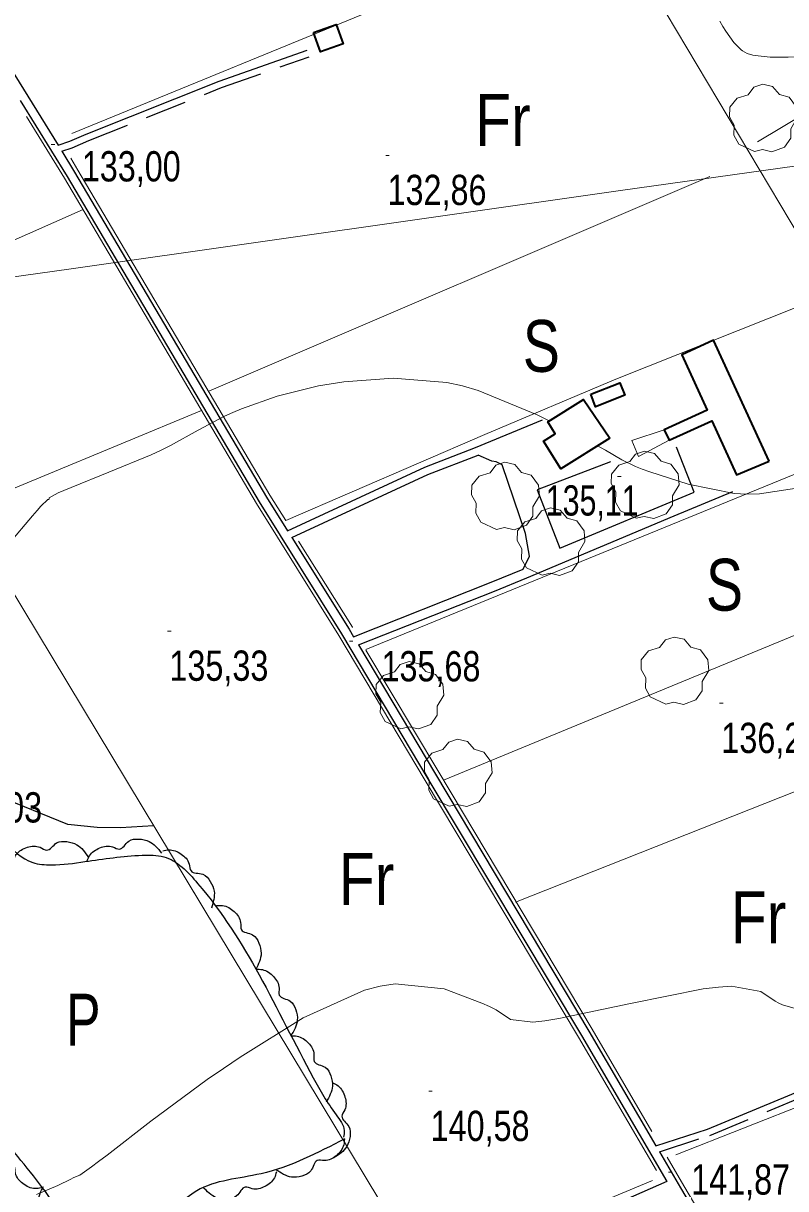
# Model space of a CAD drawing. Extents: x 487425 to 492029, y 4383576 to 4386788.
# Drawn here: x 489184.7 to 489405.2, y 4384585.2 to 4384922.2 of the extents above; entities that cross this region are included whole.
import ezdxf
from ezdxf.enums import TextEntityAlignment as Align

# ---------------------------------------------------------------- set-up
doc = ezdxf.new("R2010")
doc.units = 0
doc.header["$LTSCALE"] = 4
doc.linetypes.add('LONG_DASHED', pattern=[7.5, 6, -1.5])
doc.linetypes.add('MEDIUM_DASHED', pattern=[4.5, 3, -1.5])
for name, color, linetype, lineweight in [('24', 7, 'Continuous', 13), ('25', 7, 'LONG_DASHED', 25), ('27', 7, 'Continuous', 25), ('29', 7, 'Continuous', 13), ('38', 7, 'Continuous', 25), ('47', 7, 'Continuous', 35), ('51', 7, 'Continuous', 13), ('7', 7, 'Continuous', 13), ('9', 7, 'Continuous', 13)]:
    doc.layers.add(name, color=color, linetype=linetype, lineweight=lineweight)
doc.layers.add('31', color=7, linetype='Continuous')

msp = doc.modelspace()

# ---------------------------------------------------------------- linework, layer by layer
at = {"layer": '24'}
msp.add_lwpolyline([(488954.49, 4384817.11), (489198.5, 4384851.16), (489357.39, 4384873.86), (489601.4, 4384907.91), (489794.34, 4384879.53), (490083.75, 4384822.79), (490248.31, 4384800.09), (490395.85, 4384817.11), (490526.37, 4384822.79), (490764.71, 4384947.63), (491088.16, 4385117.87), (491252.72, 4385202.99), (491256.7, 4385199.2)], dxfattribs=at)
at = {"layer": '25'}
msp.add_lwpolyline([(489222.36, 4384690.19), (489212.78, 4384689.59), (489206.03, 4384689.67), (489197.56, 4384690.51), (489164.93, 4384703.86), (489153.06, 4384702.65), (489149.95, 4384699.31), (489143.37, 4384687.6), (489140.48, 4384684.41)], dxfattribs=at)
at = {"layer": '27'}
for points in [[(489277.55, 4384599.65), (489253.43, 4384589.57), (489234.85, 4384584.61), (489229.17, 4384580.47), (489221.96, 4384572.75), (489221.7, 4384569.75), (489218.14, 4384566.64), (489212.8, 4384565.88), (489207.48, 4384566.39), (489199.58, 4384570.83), (489195.68, 4384577.18), (489182.16, 4384595.71), (489170.8, 4384606.34), (489161.36, 4384607.13), (489156.68, 4384605.3), (489150.43, 4384602.52), (489140.52, 4384602.56), (489136.88, 4384605.9), (489134.6, 4384609.23), (489133.91, 4384614.79), (489136.48, 4384623.16), (489142.17, 4384628.65), (489151.82, 4384632.89), (489159.74, 4384636.18), (489165.7, 4384639.11), (489160.81, 4384651.84), (489154, 4384659.2), (489144.07, 4384670.19), (489139.87, 4384677.29), (489142.09, 4384681.32), (489153.12, 4384687.94), (489165.33, 4384692.98), (489178.98, 4384685.7), (489187.39, 4384679.53), (489192.78, 4384678.86), (489202.47, 4384679.8), (489219.07, 4384681.64), (489225.29, 4384681.2), (489235.11, 4384673.51), (489252.89, 4384647.05), (489268.53, 4384617.31), (489275.16, 4384606.58), (489277.51, 4384602.05), (489277.33, 4384600.1)], [(489181.81, 4384680.34), (489182.66, 4384681.89), (489185.86, 4384683.94), (489189.55, 4384683.94), (489191.43, 4384683.13), (489194.33, 4384685.19), (489197.29, 4384685.58), (489200.18, 4384684.69), (489203.5, 4384681)], [(489203.08, 4384679.86), (489203.81, 4384681.48), (489206.83, 4384683.77), (489210.51, 4384684.07), (489212.46, 4384683.41), (489215.18, 4384685.69), (489218.1, 4384686.32), (489221.05, 4384685.66), (489224.65, 4384682.25)], [(489224.99, 4384682.9), (489226.74, 4384683.21), (489230.33, 4384681.99), (489232.64, 4384679.11), (489233.19, 4384677.13), (489236.61, 4384676.16), (489238.77, 4384674.1), (489239.88, 4384671.29), (489239.07, 4384666.39)], [(489240.55, 4384667.08), (489242.32, 4384667.11), (489245.68, 4384665.35), (489247.53, 4384662.16), (489247.76, 4384660.12), (489250.99, 4384658.63), (489252.81, 4384656.26), (489253.47, 4384653.31), (489251.92, 4384648.6)], [(489252.05, 4384648.67), (489253.82, 4384648.58), (489257.05, 4384646.58), (489258.65, 4384643.25), (489258.73, 4384641.2), (489261.85, 4384639.48), (489263.48, 4384636.98), (489263.93, 4384633.99), (489262.04, 4384629.41)], [(489262.08, 4384629.43), (489263.85, 4384629.35), (489267.1, 4384627.38), (489268.73, 4384624.08), (489268.84, 4384622.03), (489271.97, 4384620.34), (489273.63, 4384617.86), (489274.11, 4384614.87), (489272.27, 4384610.27)], [(489274.17, 4384615.85), (489275.72, 4384614.97), (489277.71, 4384611.74), (489277.65, 4384608.05), (489276.81, 4384606.18), (489278.83, 4384603.25), (489279.18, 4384600.29), (489278.24, 4384597.41), (489274.5, 4384594.15)], [(489189.84, 4384585.45), (489188.08, 4384585.26), (489184.57, 4384586.7), (489182.44, 4384589.72), (489182.03, 4384591.73), (489178.68, 4384592.92), (489176.66, 4384595.12), (489175.73, 4384598), (489176.84, 4384602.83)], [(489277.55, 4384599.65), (489277.36, 4384597.89), (489275.18, 4384594.78), (489271.77, 4384593.36), (489269.72, 4384593.39), (489267.83, 4384590.38), (489265.25, 4384588.89), (489262.24, 4384588.6), (489257.76, 4384590.74)], [(489257.88, 4384590.09), (489257.31, 4384588.41), (489254.51, 4384585.85), (489250.88, 4384585.21), (489248.88, 4384585.69), (489246.38, 4384583.16), (489243.53, 4384582.26), (489240.53, 4384582.64), (489236.63, 4384585.7)], [(489201.54, 4384567.2), (489199.77, 4384567.2), (489196.44, 4384569.03), (489194.67, 4384572.27), (489194.48, 4384574.31), (489191.28, 4384575.87), (489189.52, 4384578.27), (489188.91, 4384581.24), (489190.56, 4384585.92)]]:
    msp.add_spline(points, degree=3, dxfattribs=at)
at = {"layer": '29'}
for points in [[(489396.16, 4384885.12), (489391.62, 4384887.24), (489390.21, 4384889.78), (489390.31, 4384892.76), (489388.94, 4384895.17), (489388.98, 4384897.92), (489391.14, 4384900.52), (489394.33, 4384901.52), (489395.98, 4384903.71), (489398.55, 4384904.54), (489401.41, 4384903.89), (489403.36, 4384901.62), (489406.17, 4384900.8), (489408.3, 4384897.95), (489408.54, 4384894.82), (489406.66, 4384891.67), (489406.66, 4384888.99), (489404.84, 4384886.38), (489401.22, 4384885.04), (489398.45, 4384885.67)], [(489361.95, 4384779.05), (489357.41, 4384781.17), (489356, 4384783.71), (489356.1, 4384786.69), (489354.73, 4384789.1), (489354.77, 4384791.85), (489356.93, 4384794.45), (489360.12, 4384795.45), (489361.77, 4384797.64), (489364.34, 4384798.47), (489367.2, 4384797.82), (489369.15, 4384795.55), (489371.96, 4384794.73), (489374.09, 4384791.88), (489374.33, 4384788.75), (489372.45, 4384785.6), (489372.45, 4384782.92), (489370.63, 4384780.31), (489367.01, 4384778.97), (489364.24, 4384779.6)], [(489321.55, 4384775.84), (489317.01, 4384777.96), (489315.6, 4384780.5), (489315.7, 4384783.48), (489314.33, 4384785.89), (489314.37, 4384788.64), (489316.53, 4384791.24), (489319.72, 4384792.24), (489321.37, 4384794.43), (489323.94, 4384795.26), (489326.8, 4384794.61), (489328.75, 4384792.34), (489331.56, 4384791.52), (489333.69, 4384788.67), (489333.93, 4384785.54), (489332.05, 4384782.39), (489332.05, 4384779.71), (489330.23, 4384777.1), (489326.61, 4384775.76), (489323.84, 4384776.39)], [(489334.75, 4384762.63), (489330.21, 4384764.75), (489328.8, 4384767.29), (489328.9, 4384770.27), (489327.53, 4384772.68), (489327.57, 4384775.43), (489329.73, 4384778.03), (489332.92, 4384779.03), (489334.57, 4384781.22), (489337.14, 4384782.05), (489340, 4384781.4), (489341.95, 4384779.13), (489344.76, 4384778.31), (489346.89, 4384775.46), (489347.13, 4384772.33), (489345.25, 4384769.18), (489345.25, 4384766.5), (489343.43, 4384763.89), (489339.81, 4384762.55), (489337.04, 4384763.18)], [(489370.56, 4384725.31), (489366.02, 4384727.43), (489364.61, 4384729.97), (489364.71, 4384732.95), (489363.34, 4384735.36), (489363.38, 4384738.11), (489365.54, 4384740.71), (489368.73, 4384741.71), (489370.38, 4384743.9), (489372.95, 4384744.73), (489375.81, 4384744.08), (489377.76, 4384741.81), (489380.57, 4384740.99), (489382.7, 4384738.14), (489382.94, 4384735.01), (489381.06, 4384731.86), (489381.06, 4384729.18), (489379.24, 4384726.57), (489375.62, 4384725.23), (489372.85, 4384725.86)], [(489293.89, 4384718.23), (489289.35, 4384720.35), (489287.94, 4384722.89), (489288.04, 4384725.87), (489286.67, 4384728.28), (489286.71, 4384731.03), (489288.87, 4384733.63), (489292.06, 4384734.63), (489293.71, 4384736.82), (489296.28, 4384737.65), (489299.14, 4384737), (489301.09, 4384734.73), (489303.9, 4384733.91), (489306.03, 4384731.06), (489306.27, 4384727.93), (489304.39, 4384724.78), (489304.39, 4384722.1), (489302.57, 4384719.49), (489298.95, 4384718.15), (489296.18, 4384718.78)], [(489307.89, 4384695.79), (489303.35, 4384697.91), (489301.94, 4384700.45), (489302.04, 4384703.43), (489300.67, 4384705.84), (489300.71, 4384708.59), (489302.87, 4384711.19), (489306.06, 4384712.19), (489307.71, 4384714.38), (489310.28, 4384715.21), (489313.14, 4384714.56), (489315.09, 4384712.29), (489317.9, 4384711.47), (489320.03, 4384708.62), (489320.27, 4384705.49), (489318.39, 4384702.34), (489318.39, 4384699.66), (489316.57, 4384697.05), (489312.95, 4384695.71), (489310.18, 4384696.34)]]:
    msp.add_lwpolyline(points, close=True, dxfattribs=at)
at = {"layer": '38'}
for p, q in [((489170.75, 4384925.69), (489194.73, 4384886.93)), ((489315.44, 4384799.49), (489334.84, 4384807.49))]:
    msp.add_line(p, q, dxfattribs=at)
for points in [[(489194.73, 4384886.93), (489198.15, 4384888.06), (489202.87, 4384890.1), (489241.34, 4384905.42), (489266.74, 4384914.37)], [(489183.8, 4384899.8), (489197.37, 4384877.86), (489252.87, 4384783.82), (489276.74, 4384745.66), (489301.69, 4384703.76), (489346.08, 4384629.51), (489370.77, 4384587.28)], [(489195.79, 4384885.19), (489199.53, 4384879.16), (489255.03, 4384785.13), (489261.07, 4384775.47)], [(489354.5, 4384795.41), (489333.33, 4384787.32), (489339.82, 4384770.44), (489378.71, 4384786.58), (489373.61, 4384799.62)], [(489261.07, 4384775.47), (489300.77, 4384793.86), (489315.44, 4384799.49)], [(489262.31, 4384773.5), (489301.67, 4384791.73), (489316.27, 4384797.33)], [(489329.3, 4384764.35), (489331.09, 4384768.14), (489329.96, 4384774.68), (489323.21, 4384794.49), (489321.42, 4384795.41), (489320.22, 4384795.57), (489316.27, 4384797.33)], [(489330.33, 4384761.82), (489372.93, 4384779.74), (489389.89, 4384786.83)], [(489262.31, 4384773.5), (489278.9, 4384746.97), (489280.17, 4384744.83)], [(489280.17, 4384744.83), (489319.96, 4384760.55), (489329.3, 4384764.35)], [(489281.59, 4384742.45), (489320.98, 4384758.02), (489330.33, 4384761.82)], [(489281.59, 4384742.45), (489303.86, 4384705.05), (489348.25, 4384630.8), (489367.64, 4384597.63)], [(489367.64, 4384597.63), (489382.56, 4384602.47), (489445.51, 4384628.61), (489457.19, 4384632.29), (489461.39, 4384634.58), (489465.02, 4384636.38), (489465.58, 4384636.77), (489465.71, 4384637.21), (489465.67, 4384639.99), (489465.55, 4384642.66), (489464.96, 4384645.97), (489464.22, 4384648.01), (489461.82, 4384653.47)], [(489368.64, 4384595.92), (489374.74, 4384585.48), (489411.37, 4384523.66)], [(489370.77, 4384587.28), (489325.05, 4384567.16), (489254.49, 4384537.14), (489177.06, 4384504.55), (489124.2, 4384480.1), (489117.67, 4384477.31)]]:
    msp.add_lwpolyline(points, dxfattribs=at)
at = {"layer": '38', "linetype": 'MEDIUM_DASHED'}
for points in [[(489195.79, 4384885.19), (489198.85, 4384886.21), (489203.63, 4384888.27), (489242.03, 4384903.57), (489267.39, 4384912.5)], [(489368.64, 4384595.92), (489383.24, 4384600.64), (489446.18, 4384626.78), (489457.95, 4384630.49), (489462.29, 4384632.86), (489466.02, 4384634.7), (489467.27, 4384635.58), (489467.65, 4384636.96), (489467.61, 4384640.05), (489467.49, 4384642.87), (489466.84, 4384646.48), (489466.02, 4384648.73), (489463.59, 4384654.25)]]:
    msp.add_lwpolyline(points, dxfattribs=at)
at = {"layer": '47'}
for points in [[(489268.66, 4384919.5), (489275.17, 4384921.84), (489277.18, 4384916.25), (489270.67, 4384913.91)], [(489400.42, 4384795.56), (489384.31, 4384830.55), (489375.1, 4384826.32), (489382.43, 4384810.35), (489370.08, 4384804.68), (489371.47, 4384801.63), (489383.84, 4384807.27), (489390.96, 4384791.65)], [(489348.8, 4384814.9), (489357.21, 4384818.21), (489358.62, 4384814.64), (489350.21, 4384811.33)], [(489354.28, 4384802.24), (489340.15, 4384793.4), (489335.16, 4384801.36), (489338.55, 4384803.49), (489336.37, 4384806.95), (489346.68, 4384813.44)]]:
    msp.add_lwpolyline(points, close=True, dxfattribs=at)
at = {"layer": '51'}
for p, q in [((489198.71, 4384890.28), (489352.25, 4384953.28)), ((489238.3, 4384815.79), (489383.28, 4384877.91)), ((488997.94, 4384778.6), (489201.96, 4384868.29)), ((489283.74, 4384741.15), (489441.19, 4384805.45)), ((489306.2, 4384703.33), (489465.61, 4384769.16)), ((489327.02, 4384668.03), (489486.26, 4384731.12)), ((489373.38, 4384595.04), (489533.74, 4384658.11))]:
    msp.add_line(p, q, dxfattribs=at)
for points in [[(489070.32, 4385428.68), (489128.85, 4385330.93), (489151.38, 4385292.79), (489173.15, 4385255.18), (489216.83, 4385183.94), (489248.06, 4385133.09), (489278.19, 4385084.29), (489307.53, 4385031.89), (489352.72, 4384955.3), (489418.46, 4384844.95), (489468.83, 4384761.92), (489515.01, 4384686.08), (489572.92, 4384586.84), (489624.62, 4384501.7), (489685.23, 4384402.81), (489777.59, 4384250.81)], [(489397.04, 4384887.88), (489498.11, 4384948.32), (489554.55, 4384983.01), (489613.25, 4385019.48)], [(489185.56, 4384895.21), (489196.58, 4384877.39), (489252.09, 4384783.34), (489275.96, 4384745.18), (489300.9, 4384703.29), (489345.29, 4384629.04), (489367.84, 4384590.48)], [(489198.39, 4384883.16), (489200.49, 4384879.74), (489255.98, 4384785.71), (489260.57, 4384778.4)], [(489418.38, 4384844.05), (489356.05, 4384819.32), (489318.21, 4384803.25), (489260.57, 4384778.4)], [(489236.25, 4384810.18), (489166.41, 4384781.27), (489097.95, 4384751.06), (489041.4, 4384725.82), (489034.99, 4384723.05), (489029.25, 4384720.11), (488992.32, 4384678.89), (488988.14, 4384673.77), (488987.22, 4384672.28), (488986.75, 4384670.86), (488986.18, 4384666.51), (488986, 4384631.03), (488986.04, 4384627.95), (488986.39, 4384625.4), (488986.66, 4384623.37), (489008.55, 4384574.95)], [(489370.08, 4384804.68), (489360.73, 4384801.56), (489362.62, 4384796.89), (489371.47, 4384801.63)], [(489366.62, 4384587.61), (489300.81, 4384560.15), (489167.19, 4384781.6)], [(489264.26, 4384772.48), (489279.85, 4384747.55), (489279.88, 4384747.51)], [(489283.77, 4384740.98), (489304.82, 4384705.62), (489349.2, 4384631.37), (489366.49, 4384601.81)], [(489370.87, 4384594.31), (489375.69, 4384586.05), (489411.63, 4384525.42)]]:
    msp.add_lwpolyline(points, dxfattribs=at)
at = {"layer": '7'}
for p, q in [((489192.77, 4384887.12), (489193.77, 4384887.12)), ((489289.52, 4384883.99), (489290.52, 4384883.99)), ((489356.58, 4384791.1), (489357.58, 4384791.1)), ((489226.43, 4384746.45), (489227.43, 4384746.45)), ((489278.99, 4384743.52), (489279.99, 4384743.52)), ((489386.07, 4384725.57), (489387.07, 4384725.57)), ((489301.97, 4384613.4), (489302.97, 4384613.4)), ((489371.32, 4384590.03), (489372.32, 4384590.03))]:
    msp.add_line(p, q, dxfattribs=at)
at = {"layer": '9'}
for points in [[(489386.16, 4384922.78), (489387.03, 4384921.24), (489387.83, 4384919.89), (489390.15, 4384916.62), (489391.89, 4384914.91), (489392.31, 4384914.54), (489392.72, 4384914.22), (489394, 4384913.43), (489395.72, 4384912.98), (489396.4, 4384912.86), (489397.18, 4384912.75), (489400.72, 4384912.39), (489405.86, 4384912.36), (489407.64, 4384912.46), (489409.57, 4384912.6), (489417.82, 4384913.5), (489426.51, 4384914.93), (489428.71, 4384915.42), (489430.83, 4384915.94), (489437.73, 4384918.14), (489443.76, 4384920.93), (489445.32, 4384921.82), (489446.84, 4384922.77)], [(489180.51, 4384771.69), (489187.32, 4384779.8), (489188.66, 4384781.34), (489189.76, 4384782.57), (489191.73, 4384784.49), (489192.06, 4384784.53), (489192.11, 4384784.57), (489192.15, 4384784.63), (489192.18, 4384784.98), (489194.78, 4384786.38), (489196.45, 4384787.11), (489198.53, 4384787.98), (489209.44, 4384792.35), (489221.68, 4384797.45), (489224.58, 4384798.79), (489227.28, 4384800.08), (489235.29, 4384804.49), (489242.84, 4384808.55), (489245.24, 4384809.63), (489247.79, 4384810.69), (489258.12, 4384814.37), (489270.1, 4384817.34), (489273.68, 4384817.95), (489277.37, 4384818.47), (489291.67, 4384819.61), (489307.21, 4384818.32), (489311.69, 4384817.31), (489316.24, 4384816.01), (489333.32, 4384808.99), (489336.79, 4384807.21)], [(489350.74, 4384800.02), (489353.09, 4384798.76), (489357.82, 4384795.93), (489361.73, 4384794.02), (489363.63, 4384793.3), (489365.87, 4384792.49), (489376.93, 4384788.89), (489390.26, 4384786.25), (489393.94, 4384786.06), (489397.62, 4384786.1), (489410.89, 4384788.18), (489422.8, 4384790.94), (489425.63, 4384791.41), (489428.26, 4384791.75), (489436.06, 4384791.92), (489441.91, 4384792.31), (489443.32, 4384792.79), (489444.63, 4384793.44)], [(489188.51, 4384583.52), (489194.66, 4384586.12), (489198.38, 4384587.98), (489199.12, 4384588.34), (489199.75, 4384588.63), (489201.01, 4384589.12), (489204.45, 4384591.55), (489206.45, 4384593.06), (489208.91, 4384594.94), (489221.58, 4384604.78), (489237.85, 4384616.78), (489242.58, 4384620.03), (489247.41, 4384623.25), (489265.65, 4384634.59), (489283.37, 4384642.65), (489287.88, 4384643.8), (489292.21, 4384644.48), (489306.39, 4384643.02), (489317.26, 4384638.91), (489319.51, 4384637.92), (489321.42, 4384636.99), (489325.56, 4384634.15), (489332.08, 4384633.39), (489335.49, 4384633.77), (489339.6, 4384634.4), (489360.25, 4384638.79), (489381.36, 4384643.01), (489385.76, 4384643.52), (489389.53, 4384643.75), (489397.95, 4384642.23), (489402.11, 4384639.43), (489403.21, 4384638.86), (489404.29, 4384638.37), (489407.97, 4384637.35)]]:
    msp.add_lwpolyline(points, dxfattribs=at)

# ---------------------------------------------------------------- texts
at = {"layer": '31'}
for s, width, p in [('Fr', 0.85, (489323.41, 4384886.74)), ('S', 0.8, (489334.51, 4384821.4)), ('S', 0.8, (489387.48, 4384752.36)), ('Fr', 0.85, (489283.97, 4384667.3)), ('Fr', 0.85, (489397.34, 4384656.2)), ('P', 0.75, (489202.02, 4384626.61))]:
    msp.add_text(s, height=15, dxfattribs=dict(at, width=width)).set_placement(p, align=Align.CENTER)
at = {"layer": '7'}
for s, width, p in [('133,00', 0.8, (489201.59, 4384876.45)), ('132,86', 0.8, (489290.02, 4384869.62)), ('135,11', 0.75, (489335.8, 4384779.85)), ('135,33', 0.8, (489226.93, 4384732.08)), ('135,68', 0.8, (489288.27, 4384731.92)), ('136,22', 0.8, (489386.57, 4384711.2)), ('135,03', 0.8, (489161.5, 4384691.11)), ('140,58', 0.8, (489302.47, 4384599.03)), ('141,87', 0.8, (489377.83, 4384583.53))]:
    msp.add_text(s, height=8.75, dxfattribs=dict(at, width=width)).set_placement(p)

doc.saveas('drawing.dxf')
